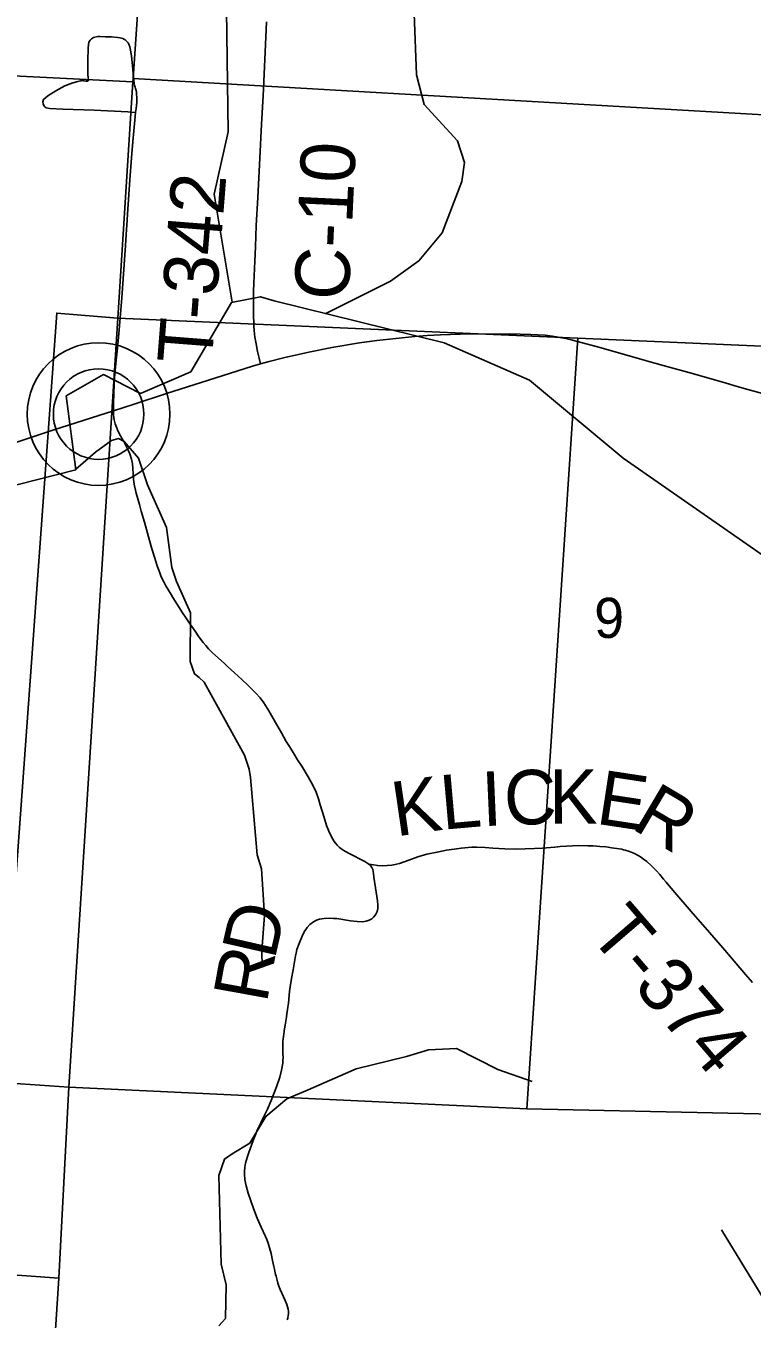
# Model space of a CAD drawing. Extents: x 0 to 34, y 0 to 22.
# Drawn here: x 25.392 to 26.149, y 17.797 to 19.146 of the extents above; entities that cross this region are included whole.
import ezdxf

# ---------------------------------------------------------------- set-up
doc = ezdxf.new("R2010")
doc.units = 0
for name, color, linetype in [('GM_X_County_Road', 7, 'Continuous'), ('GM_X_County_Road_Text', 7, 'Continuous'), ('GM_X_Minor_River', 7, 'Continuous'), ('GM_X_Section', 7, 'Continuous'), ('GM_X_Section_Text', 7, 'Continuous'), ('GM_X_State_Route', 7, 'Continuous'), ('GM_X_Township_Road', 7, 'Continuous'), ('GM_X_Township_Road_Text', 7, 'Continuous'), ('GM_X_Unincorporated', 7, 'Continuous'), ('GM_X_Unincorporated_Location', 7, 'Continuous')]:
    doc.layers.add(name, color=color, linetype=linetype)

msp = doc.modelspace()

# ---------------------------------------------------------------- linework, layer by layer
at = {"layer": 'GM_X_County_Road'}
msp.add_lwpolyline([(25.6368, 18.7932), (25.6352, 18.7992), (25.6337, 18.806), (25.6321, 18.814), (25.631, 18.8212), (25.6303, 18.8279), (25.6299, 18.8327), (25.6297, 18.8372), (25.6295, 18.8423), (25.6294, 18.8688), (25.6297, 18.8775), (25.6307, 18.9004), (25.6314, 18.9153), (25.6324, 18.9377), (25.6339, 18.9668), (25.636, 19.0078), (25.6379, 19.0432), (25.6395, 19.0729), (25.6415, 19.1182), (25.643, 19.1499)], dxfattribs=at)
at = {"layer": 'GM_X_Minor_River'}
for points in [[(25.6073, 18.8574), (25.5886, 18.9702), (25.6029, 19.0352), (25.6012, 19.1623), (25.5582, 19.2276), (25.4917, 19.2911), (25.4923, 19.3594), (25.4708, 19.4097), (25.4737, 19.5938), (25.4713, 19.6579), (25.427, 19.7941), (25.4053, 19.9981), (25.349, 20.1513), (25.3065, 20.2086), (25.115, 20.2805), (25.1008, 20.2933), (25.0631, 20.3317), (24.9228, 20.3456), (24.7364, 20.2301), (24.7153, 20.2204)], [(25.7041, 18.8455), (25.7723, 18.8794), (25.8019, 18.9007), (25.8261, 18.93), (25.8466, 18.9836), (25.8493, 19.0034), (25.8421, 19.0258), (25.8072, 19.0638), (25.7993, 19.0946), (25.797, 19.1588)], [(25.3826, 18.667), (25.4443, 18.6827), (25.4342, 18.7597), (25.473, 18.782), (25.5116, 18.7623), (25.564, 18.7848), (25.6067, 18.8573), (25.6367, 18.8632), (25.6511, 18.8588), (25.8282, 18.8152), (25.9172, 18.7762), (26.0147, 18.6947), (26.1917, 18.5718), (26.293, 18.4884), (26.3885, 18.4475), (26.5595, 18.4005)], [(25.4442, 18.6835), (25.4648, 18.7011), (25.4815, 18.7133), (25.4887, 18.7152), (25.4948, 18.7122), (25.5095, 18.6947), (25.519, 18.667), (25.5387, 18.6225), (25.5444, 18.5807), (25.5493, 18.5663), (25.5637, 18.5336), (25.5633, 18.4826), (25.5678, 18.4697), (25.5728, 18.4659), (25.5781, 18.4613), (25.6201, 18.385), (25.625, 18.3705), (25.6265, 18.3618), (25.6333, 18.2812), (25.6379, 18.2664), (25.6409, 18.2177), (25.6382, 18.1812), (25.6386, 18.1637)], [(25.5934, 17.7899), (25.6002, 17.7975), (25.601, 17.8325), (25.5957, 17.8542), (25.5934, 17.9466), (25.5991, 17.9637), (25.6071, 17.969), (25.6256, 17.9804), (25.6423, 18.0082), (25.6643, 18.0265), (25.6863, 18.036), (25.7364, 18.0577), (25.7891, 18.0707), (25.8118, 18.0776), (25.841, 18.0791), (25.8842, 18.0571), (25.9198, 18.0446)], [(26.8939, 17.8041), (26.8093, 17.8831), (26.7577, 17.9938), (26.6748, 18.0364), (26.663, 18.0393), (26.4885, 17.9971), (26.3926, 17.9568), (26.3196, 17.8836), (26.2691, 17.7955), (26.221, 17.7841), (26.1738, 17.7969), (26.1172, 17.8898)]]:
    msp.add_lwpolyline(points, dxfattribs=at)
at = {"layer": 'GM_X_Section'}
for points in [[(24.5388, 20.1708), (25.5703, 20.1097), (25.5433, 19.6923), (25.5164, 19.2759), (25.5041, 19.0909), (25.5038, 19.0874), (24.9075, 19.1174), (24.4668, 19.1382), (24.4804, 19.3317), (24.5096, 19.7459)], [(25.5164, 19.2759), (26.5757, 19.2125), (26.5652, 19.0298), (25.5041, 19.0909)], [(24.9075, 19.1174), (25.5038, 19.0874), (25.4882, 18.8408), (25.4244, 18.8461), (25.3836, 18.2803), (24.8626, 18.3102)], [(25.5038, 19.0874), (25.5041, 19.0909), (26.5652, 19.0298), (26.551, 18.7947), (25.9675, 18.82), (25.4882, 18.8408)], [(25.4882, 18.8408), (25.4369, 18.0387), (25.3665, 18.0434), (25.3836, 18.2803), (25.4244, 18.8461)], [(25.9675, 18.82), (25.9143, 18.0162), (25.4369, 18.0387), (25.4882, 18.8408)], [(26.551, 18.7947), (26.4949, 18.0036), (25.9143, 18.0162), (25.9675, 18.82)], [(24.3998, 18.1092), (25.3665, 18.0434), (25.4369, 18.0387), (25.4267, 17.8394), (24.3871, 17.9146)], [(25.4369, 18.0387), (25.9143, 18.0162), (26.4949, 18.0036), (26.4248, 16.9831), (25.8848, 17.0085), (25.3722, 17.0086), (25.3999, 17.4262), (25.4267, 17.8394)], [(25.4267, 17.8394), (25.3999, 17.4262), (24.3605, 17.505), (24.3871, 17.9146)]]:
    msp.add_lwpolyline(points, close=True, dxfattribs=at)
at = {"layer": 'GM_X_State_Route'}
msp.add_lwpolyline([(25.3724, 18.7081), (25.4212, 18.7244), (25.4836, 18.7443), (25.5051, 18.7511), (25.5389, 18.7624), (25.5827, 18.7762), (25.6284, 18.7908), (25.6368, 18.7932), (25.6459, 18.7956), (25.6606, 18.7994), (25.6873, 18.8054), (25.711, 18.8102), (25.7398, 18.815), (25.7582, 18.8175), (25.7977, 18.8217), (25.8104, 18.8227), (25.8244, 18.8234), (25.8448, 18.8242), (25.8964, 18.8244), (25.9187, 18.824), (25.9335, 18.8231), (25.9409, 18.8221), (25.9549, 18.8197), (25.9621, 18.818), (25.992, 18.8099), (26.0391, 18.7965), (26.0565, 18.7916), (26.087, 18.7831), (26.1222, 18.773), (26.1335, 18.7697), (26.1448, 18.7666), (26.1717, 18.7592)], dxfattribs=at)
at = {"layer": 'GM_X_Township_Road'}
for points in [[(25.5065, 19.0554), (25.507, 19.0596), (25.5077, 19.0662), (25.5078, 19.0686), (25.5079, 19.0714), (25.5076, 19.0742), (25.5074, 19.0766), (25.5071, 19.0783), (25.5065, 19.0805), (25.506, 19.0818), (25.5054, 19.0835), (25.5051, 19.0853), (25.5046, 19.089), (25.5044, 19.0914), (25.5037, 19.1001), (25.5031, 19.1077), (25.5023, 19.1143), (25.5016, 19.1186), (25.501, 19.1223), (25.5005, 19.124), (25.4994, 19.1268), (25.4987, 19.1282), (25.4965, 19.1305), (25.4956, 19.1313), (25.4944, 19.1319), (25.4933, 19.1325), (25.492, 19.1329), (25.4904, 19.1334), (25.4882, 19.1337), (25.4814, 19.1343), (25.4783, 19.1343), (25.4753, 19.1344), (25.4693, 19.1347), (25.4673, 19.1346), (25.4641, 19.1341), (25.4628, 19.1337), (25.4606, 19.1323), (25.4593, 19.1309), (25.4579, 19.1287), (25.4574, 19.1262), (25.4571, 19.1226), (25.457, 19.1189), (25.4569, 19.1128), (25.4569, 19.0954), (25.4571, 19.0916), (25.4573, 19.0894), (25.4573, 19.0888), (25.4568, 19.0881), (25.4557, 19.088), (25.4548, 19.0882), (25.4527, 19.0886), (25.4515, 19.0887), (25.4503, 19.0886), (25.4492, 19.0884), (25.4464, 19.0879), (25.4412, 19.0862), (25.4329, 19.0831), (25.4233, 19.0779), (25.4151, 19.0728), (25.4126, 19.0708), (25.4107, 19.069), (25.41, 19.0664), (25.4102, 19.0644), (25.4109, 19.0626), (25.4117, 19.0615), (25.4132, 19.0602), (25.417, 19.0596), (25.4308, 19.059), (25.4632, 19.0578), (25.4986, 19.056), (25.5065, 19.0554)], [(25.4971, 18.9336), (25.4974, 18.9376), (25.4981, 18.9493), (25.4995, 18.9697), (25.5006, 18.9851), (25.5023, 19.008), (25.5036, 19.0253), (25.5058, 19.0474), (25.5065, 19.0554)], [(25.4836, 18.7443), (25.4835, 18.7521), (25.4837, 18.7621), (25.4841, 18.772), (25.4849, 18.7832), (25.4868, 18.8002), (25.4876, 18.8095), (25.4893, 18.8287), (25.4921, 18.862), (25.4959, 18.9168), (25.4971, 18.9336)], [(25.6172, 18.4639), (25.6098, 18.4708), (25.6025, 18.4776), (25.5993, 18.4805), (25.5865, 18.4922), (25.5826, 18.4961), (25.5797, 18.4993), (25.5769, 18.5026), (25.5725, 18.5086), (25.5686, 18.5142), (25.5633, 18.5218), (25.5598, 18.5269), (25.5547, 18.5347), (25.552, 18.5389), (25.5455, 18.5495), (25.5436, 18.5527), (25.5382, 18.5617), (25.5363, 18.5651), (25.5346, 18.5682), (25.533, 18.5722), (25.5318, 18.5752), (25.5308, 18.5779), (25.5295, 18.5814), (25.5259, 18.5927), (25.5227, 18.6027), (25.5189, 18.6165), (25.5157, 18.628), (25.5125, 18.6394), (25.5105, 18.6464), (25.5071, 18.6583), (25.5063, 18.6614), (25.5053, 18.6661), (25.5047, 18.6697), (25.5042, 18.6728), (25.5038, 18.684), (25.5033, 18.689), (25.5023, 18.6939), (25.5005, 18.6992), (25.4991, 18.7025), (25.4975, 18.7061), (25.4952, 18.7104), (25.4927, 18.7149), (25.4908, 18.7182), (25.4885, 18.7225), (25.4865, 18.727), (25.4852, 18.7308), (25.4841, 18.7347), (25.4838, 18.7373), (25.4836, 18.7398), (25.4836, 18.7443)], [(25.7498, 18.2714), (25.7476, 18.2728), (25.7456, 18.2741), (25.7293, 18.2823), (25.7231, 18.286), (25.7192, 18.2888), (25.7167, 18.291), (25.7137, 18.2951), (25.7109, 18.2997), (25.7081, 18.3058), (25.7056, 18.3118), (25.703, 18.32), (25.6991, 18.3333), (25.6972, 18.3395), (25.6948, 18.3463), (25.6917, 18.3532), (25.6866, 18.3625), (25.6798, 18.3736), (25.6755, 18.3802), (25.6707, 18.3877), (25.6669, 18.394), (25.6636, 18.3994), (25.6586, 18.4082), (25.6538, 18.4167), (25.6455, 18.4312), (25.6401, 18.4397), (25.6364, 18.4447), (25.6318, 18.4498), (25.6234, 18.4581), (25.6172, 18.4639)], [(25.7498, 18.2714), (25.7544, 18.2707), (25.759, 18.2699), (25.7642, 18.2696), (25.7688, 18.2698), (25.7735, 18.2704), (25.777, 18.2709), (25.7787, 18.2714), (25.7816, 18.2721), (25.7913, 18.2756), (25.8006, 18.2789), (25.81, 18.2817), (25.8208, 18.2839), (25.8306, 18.2858), (25.8385, 18.2871), (25.8459, 18.2881), (25.8569, 18.2889), (25.8618, 18.2889), (25.8711, 18.2886), (25.8789, 18.2881), (25.8915, 18.2872), (25.9027, 18.287), (25.9125, 18.2873), (25.9225, 18.2876), (25.9306, 18.2881), (25.9349, 18.2884), (25.9435, 18.2891), (25.9466, 18.2894), (25.9491, 18.2896), (25.9559, 18.2901), (25.9682, 18.2907), (25.9781, 18.2906), (25.9837, 18.2903), (25.9905, 18.2899), (25.9966, 18.2893), (25.9991, 18.289), (26.0027, 18.2885), (26.0081, 18.2876), (26.0105, 18.2872), (26.0134, 18.2868), (26.015, 18.2862), (26.0168, 18.2858), (26.0215, 18.2844), (26.0266, 18.2823), (26.0303, 18.2802), (26.033, 18.2788), (26.036, 18.2767), (26.0395, 18.2742), (26.0445, 18.2696), (26.0492, 18.2647), (26.0529, 18.2605), (26.0567, 18.2557), (26.0596, 18.2525), (26.0627, 18.2487), (26.0648, 18.2464), (26.0687, 18.2416), (26.0857, 18.2219), (26.1048, 18.2), (26.1187, 18.1841), (26.1268, 18.1747), (26.1424, 18.1564), (26.1495, 18.1479)], [(25.6646, 17.7959), (25.6653, 17.7978), (25.6657, 17.8005), (25.666, 17.8022), (25.6658, 17.8047), (25.6656, 17.8073), (25.6642, 17.8121), (25.6625, 17.8162), (25.6574, 17.8275), (25.656, 17.8311), (25.6549, 17.8344), (25.654, 17.8374), (25.653, 17.8415), (25.6525, 17.8433), (25.6517, 17.8469), (25.6513, 17.8487), (25.6506, 17.8517), (25.6494, 17.8578), (25.6478, 17.8651), (25.6463, 17.8711), (25.6448, 17.8759), (25.6432, 17.8797), (25.642, 17.8828), (25.6375, 17.8928), (25.6334, 17.9019), (25.6294, 17.912), (25.6266, 17.9203), (25.6239, 17.9281), (25.6219, 17.9357), (25.6211, 17.9389), (25.6205, 17.9424), (25.6201, 17.9478), (25.6201, 17.9509), (25.6204, 17.9551), (25.621, 17.9593), (25.622, 17.9628), (25.6231, 17.9663), (25.6245, 17.9704), (25.6259, 17.9744), (25.6291, 17.9831), (25.6312, 17.9882), (25.6331, 17.9928), (25.641, 18.0096), (25.6439, 18.0158), (25.6478, 18.0249), (25.6536, 18.0392), (25.6569, 18.0492), (25.6588, 18.0563), (25.66, 18.0637), (25.6602, 18.0665), (25.6604, 18.0698), (25.6602, 18.0734), (25.6601, 18.0767), (25.6599, 18.0822), (25.6602, 18.0862), (25.6604, 18.089), (25.6607, 18.0914), (25.661, 18.0945), (25.6613, 18.0963), (25.6614, 18.0978), (25.6617, 18.0994), (25.6624, 18.1035), (25.663, 18.1076), (25.6637, 18.1117), (25.6643, 18.1157), (25.665, 18.1195), (25.6654, 18.1222), (25.6658, 18.1263), (25.6669, 18.1384), (25.6676, 18.1432), (25.669, 18.152), (25.6708, 18.1612), (25.6733, 18.1756), (25.6738, 18.1786), (25.6746, 18.1823), (25.6753, 18.1842), (25.6762, 18.1868), (25.6776, 18.1902), (25.6794, 18.1946), (25.6801, 18.1962), (25.6823, 18.2006), (25.6839, 18.2032), (25.6854, 18.2052), (25.6883, 18.2083), (25.6921, 18.2113), (25.6953, 18.2129), (25.6982, 18.2139), (25.703, 18.2147), (25.7091, 18.215), (25.7127, 18.2147), (25.7165, 18.2145), (25.7306, 18.2123), (25.7375, 18.2114), (25.7431, 18.2112), (25.7469, 18.2118), (25.75, 18.2128), (25.7528, 18.2143), (25.7547, 18.2159), (25.7568, 18.2184), (25.7584, 18.2219), (25.759, 18.225), (25.7592, 18.2288), (25.7588, 18.2332), (25.7566, 18.2465), (25.755, 18.2577), (25.7545, 18.2615), (25.7537, 18.2657), (25.7529, 18.268), (25.7515, 18.2699), (25.7498, 18.2714)]]:
    msp.add_lwpolyline(points, dxfattribs=at)
at = {"layer": 'GM_X_Unincorporated'}
for radius in [0.0744, 0.0472]:
    msp.add_circle((25.468, 18.7408), radius, dxfattribs=at)
at = {"layer": 'GM_X_Unincorporated_Location'}
msp.add_line((25.468, 18.7408), (25.468, 18.7408), dxfattribs=at)

# ---------------------------------------------------------------- texts
at = {"layer": 'GM_X_County_Road_Text'}
msp.add_text('C-10', height=0.05682, rotation=87.3274, dxfattribs=at).set_placement((25.7286, 18.8588))
at = {"layer": 'GM_X_Section_Text'}
msp.add_text('9', height=0.0419, rotation=0, dxfattribs=at).set_placement((25.9846, 18.5073))
at = {"layer": 'GM_X_Township_Road_Text'}
for s, height, rotation, p in [('T-342', 0.05682, 85.5174, (25.5857, 18.7917)), ('K', 0.0568, 8.2537, (25.778, 18.3001)), ('L', 0.0568, 5.0509, (25.8266, 18.3072)), ('I', 0.0568, 2.4909, (25.8683, 18.3109)), ('C', 0.0568, 1.8972, (25.8914, 18.3119)), ('K', 0.0568, 0.1056, (25.9376, 18.3134)), ('E', 0.0568, 351.3487, (25.9853, 18.3137)), ('R', 0.0568, 329.4519, (26.022, 18.3092)), ('D', 0.0568, 77.1353, (25.6514, 18.1705)), ('T-374', 0.05682, 310.6916, (25.9777, 18.1979)), ('R', 0.0568, 79.7311, (25.6432, 18.1253))]:
    msp.add_text(s, height=height, rotation=rotation, dxfattribs=at).set_placement(p)

doc.saveas('drawing.dxf')
